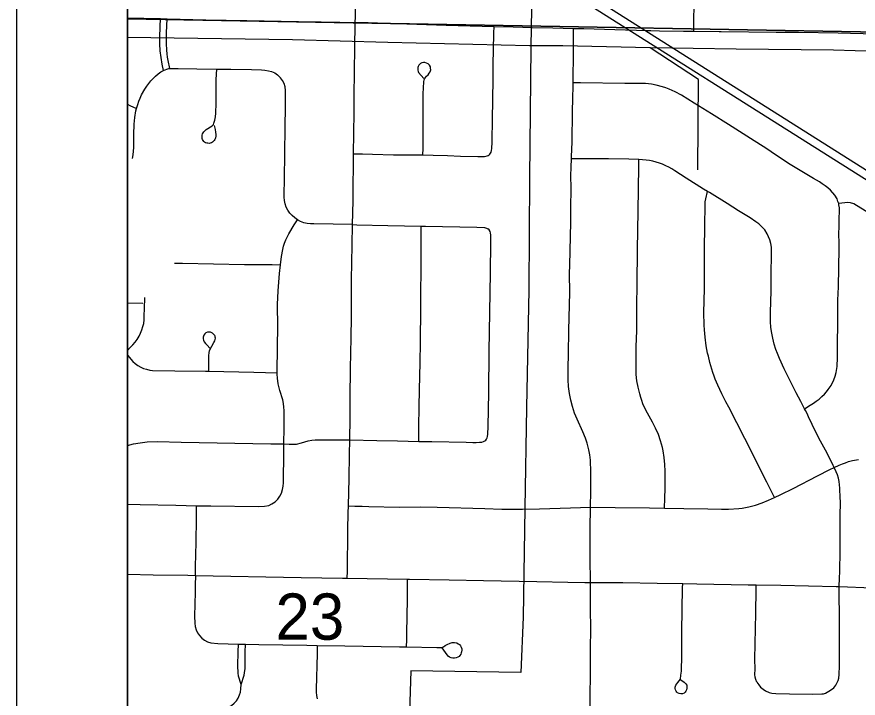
# Model space of a CAD drawing. Extents: x -59 to 43, y 0 to 22.
# Drawn here: x 23.417 to 24.177, y 17.75 to 18.366 of the extents above; entities that cross this region are included whole.
import ezdxf

# ---------------------------------------------------------------- set-up
doc = ezdxf.new("R2010")
doc.units = 0
for name, color, linetype in [('Default', 7, 'Continuous'), ('GM_X_City_Street', 7, 'Continuous'), ('GM_X_County_Road', 7, 'Continuous'), ('GM_X_Interchange_Ramps', 7, 'Continuous'), ('GM_X_Minor_River', 7, 'Continuous'), ('GM_X_Rail_Line', 7, 'Continuous'), ('GM_X_Section_Text', 7, 'Continuous'), ('GM_X_Township_Road', 7, 'Continuous'), ('SH_Data', 7, 'Continuous')]:
    doc.layers.add(name, color=color, linetype=linetype)

msp = doc.modelspace()

# ---------------------------------------------------------------- linework, layer by layer
at = {"layer": 'Default'}
for points in [[(23.51667, 19.36712), (23.51667, 18.36457), (24.19635, 18.35229), (24.21701, 19.34715)], [(23.51667, 18.36457), (23.51667, 17.35203), (23.63449, 17.34676), (24.1786, 17.34343), (24.19635, 18.35229)]]:
    msp.add_lwpolyline(points, close=True, dxfattribs=at)
at = {"layer": 'GM_X_City_Street'}
for points in [[(24.02872, 18.35333), (24.02879, 18.35839), (24.0291, 18.38136), (24.0295, 18.41121), (24.0296, 18.41847)], [(23.71539, 17.85848), (23.71547, 17.86506), (23.7159, 17.9023), (23.71623, 17.91776), (23.71641, 17.92416), (23.71676, 17.93635), (23.71699, 17.94877), (23.71733, 17.9705), (23.71758, 17.98356), (23.71794, 18.00317), (23.71803, 18.02204), (23.71833, 18.0481), (23.7189, 18.07605), (23.71917, 18.09484), (23.71937, 18.12842), (23.71978, 18.15986), (23.72017, 18.17832), (23.72061, 18.19974), (23.72071, 18.21636), (23.72092, 18.22841), (23.72112, 18.24246), (23.72165, 18.2799), (23.72171, 18.29326), (23.72194, 18.31795), (23.72215, 18.33725), (23.72263, 18.36131), (23.72271, 18.36614), (23.72307, 18.3885)], [(23.54923, 18.31778), (23.54819, 18.32346), (23.54708, 18.32952), (23.54627, 18.33563), (23.54583, 18.34177), (23.54582, 18.34793), (23.54625, 18.35716), (23.54661, 18.36474)], [(23.55509, 18.31957), (23.55362, 18.32673), (23.55299, 18.32981), (23.55253, 18.33292), (23.55223, 18.33604), (23.55199, 18.34232), (23.55208, 18.35174), (23.55227, 18.35802), (23.55247, 18.36459)], [(23.84359, 18.24157), (23.84431, 18.24217), (23.84503, 18.24307), (23.84557, 18.24403), (23.84593, 18.24535), (23.84617, 18.24721), (23.84637, 18.25298), (23.84674, 18.27474), (23.84687, 18.29002), (23.84706, 18.29607), (23.84716, 18.30538), (23.84743, 18.32386), (23.8476, 18.33621), (23.84797, 18.35139), (23.84813, 18.35765)], [(23.93517, 17.85479), (23.93488, 17.87685), (23.93491, 17.90321), (23.93525, 17.92269), (23.93563, 17.93734), (23.93573, 17.95442), (23.93526, 17.96531), (23.93474, 17.97002), (23.93387, 17.97465), (23.9323, 17.98073), (23.93084, 17.98521), (23.92844, 17.99099), (23.92327, 18.00227), (23.92093, 18.00795), (23.91899, 18.01375), (23.91747, 18.0197), (23.91629, 18.02574), (23.91549, 18.03184), (23.91503, 18.03794), (23.91524, 18.04878), (23.91538, 18.06117), (23.91548, 18.06889), (23.91566, 18.0751), (23.91572, 18.08287), (23.91656, 18.11698), (23.91646, 18.13408), (23.91654, 18.14181), (23.91743, 18.1806), (23.91741, 18.19301), (23.91768, 18.21162), (23.91762, 18.22249), (23.91781, 18.23022), (23.91812, 18.238), (23.91817, 18.23952), (23.9187, 18.25314), (23.91906, 18.28028), (23.91942, 18.29274), (23.91954, 18.3036), (23.91958, 18.30665), (23.9199, 18.33568), (23.91989, 18.35036), (23.91989, 18.35584)], [(23.78385, 18.24134), (23.78392, 18.2472), (23.7841, 18.2622), (23.784, 18.2716), (23.78398, 18.28416), (23.78416, 18.29661), (23.78448, 18.30754), (23.78489, 18.3093), (23.78538, 18.31054), (23.78608, 18.31148), (23.78716, 18.3127), (23.7885, 18.31395), (23.78953, 18.31535), (23.79031, 18.31666), (23.79064, 18.31744), (23.79084, 18.31843), (23.7908, 18.31987), (23.79051, 18.32118), (23.78965, 18.32262), (23.7885, 18.32373), (23.78718, 18.32451), (23.78554, 18.32496), (23.78435, 18.32496), (23.78296, 18.32473), (23.78159, 18.32405), (23.78065, 18.32327), (23.78004, 18.32245), (23.77946, 18.32151), (23.77922, 18.32056), (23.77909, 18.31941), (23.77917, 18.31818), (23.77942, 18.31695), (23.77987, 18.31588), (23.7846, 18.31042)], [(23.5211, 18.23809), (23.52173, 18.2416), (23.52236, 18.24805), (23.52231, 18.25378), (23.5223, 18.2599), (23.52264, 18.26908), (23.52327, 18.27517), (23.52438, 18.28119), (23.52498, 18.2835), (23.52593, 18.28711), (23.52691, 18.29001), (23.52808, 18.29284), (23.52941, 18.2956), (23.53241, 18.30094), (23.53406, 18.30352), (23.53586, 18.30599), (23.5378, 18.30835), (23.53988, 18.3106), (23.54206, 18.31276), (23.54436, 18.31476), (23.54687, 18.31652), (23.54923, 18.31778), (23.55224, 18.31896)], [(23.55224, 18.31896), (23.55407, 18.31941), (23.55509, 18.31957), (23.56243, 18.3197), (23.57941, 18.31924), (23.59738, 18.31902), (23.61021, 18.31885), (23.62872, 18.3186), (23.63797, 18.31829), (23.64103, 18.31802), (23.64405, 18.31756), (23.647, 18.3168), (23.6498, 18.31557), (23.65232, 18.3138), (23.65497, 18.31109)], [(23.59503, 18.26814), (23.59583, 18.26433), (23.59631, 18.26205), (23.59648, 18.25992), (23.59648, 18.25821), (23.59627, 18.25697), (23.59593, 18.25605), (23.59563, 18.25531), (23.59507, 18.2545), (23.59415, 18.25359), (23.59346, 18.25305), (23.59261, 18.25245), (23.59158, 18.25207), (23.59043, 18.25185), (23.58927, 18.25189), (23.5883, 18.25207), (23.58727, 18.2524), (23.58642, 18.25296), (23.5857, 18.25364), (23.58501, 18.25441), (23.58455, 18.25539), (23.58435, 18.25632), (23.58412, 18.25744), (23.58416, 18.25846), (23.58429, 18.25936), (23.58463, 18.26038), (23.58514, 18.26145), (23.58569, 18.2623), (23.58624, 18.26294), (23.58684, 18.26362), (23.58777, 18.26435), (23.59323, 18.2678), (23.59439, 18.26895), (23.59489, 18.27005), (23.59581, 18.27296), (23.59631, 18.27598), (23.59653, 18.27902), (23.59679, 18.28821), (23.59701, 18.30962), (23.59738, 18.31902)], [(23.72017, 18.17832), (23.68533, 18.17906), (23.68221, 18.17918), (23.67911, 18.17947), (23.67607, 18.18011), (23.67317, 18.18121), (23.67028, 18.18281), (23.66787, 18.18447), (23.66549, 18.18649), (23.66339, 18.18878), (23.66161, 18.19133), (23.66023, 18.19412), (23.65928, 18.19708), (23.65871, 18.20013), (23.65844, 18.20324), (23.6584, 18.20635), (23.65872, 18.21881), (23.659, 18.24373), (23.65927, 18.26529), (23.65936, 18.27182), (23.65945, 18.27938), (23.65955, 18.28732), (23.65965, 18.29668), (23.65954, 18.29981), (23.65915, 18.3029), (23.65831, 18.30587), (23.65685, 18.3086), (23.65497, 18.31109)], [(24.12881, 18.01185), (24.13397, 18.01517), (24.13676, 18.01695), (24.13947, 18.01861), (24.14191, 18.02048), (24.14452, 18.02294), (24.14697, 18.02508), (24.14871, 18.02708), (24.15019, 18.02928), (24.15282, 18.033), (24.15518, 18.03785), (24.1564, 18.04119), (24.15728, 18.0447), (24.15822, 18.04989), (24.15851, 18.05815), (24.15872, 18.06648), (24.15893, 18.09271), (24.15902, 18.11005), (24.15937, 18.1221), (24.16007, 18.15676), (24.16003, 18.16289), (24.15995, 18.16876), (24.16011, 18.178), (24.1602, 18.1842), (24.16041, 18.19036), (24.16031, 18.19339), (24.1599, 18.19636), (24.1597, 18.19752), (24.15905, 18.1994), (24.15826, 18.20158), (24.15629, 18.20489), (24.1523, 18.20954), (24.14998, 18.21157), (24.14749, 18.21344), (24.14488, 18.2152), (24.14223, 18.21692), (24.13681, 18.22009), (24.12624, 18.22638), (24.11574, 18.23284), (24.10246, 18.24136), (24.09457, 18.24677), (24.08004, 18.25621), (24.06016, 18.26884), (24.04465, 18.27863), (24.02914, 18.28823), (24.01761, 18.29529), (24.01197, 18.29835), (24.00638, 18.30095), (24.00349, 18.30208), (24.00047, 18.3031), (23.99477, 18.3046), (23.99046, 18.30541), (23.98488, 18.30597), (23.97258, 18.30593), (23.96645, 18.30587), (23.92612, 18.30654), (23.91958, 18.30665)], [(23.51667, 18.28727), (23.51894, 18.28624), (23.52498, 18.2835)], [(23.72112, 18.24246), (23.7291, 18.24227), (23.73827, 18.24204), (23.75722, 18.24159), (23.77556, 18.24159), (23.78385, 18.24134), (23.79315, 18.24107), (23.80594, 18.24075), (23.81788, 18.24037), (23.83343, 18.24011), (23.83745, 18.23994), (23.83961, 18.24006), (23.8408, 18.24029), (23.84189, 18.2406), (23.84269, 18.24097), (23.84359, 18.24157)], [(24.16021, 17.85099), (24.16044, 17.85853), (24.16062, 17.86473), (24.16077, 17.87093), (24.16087, 17.8771), (24.16095, 17.88323), (24.16094, 17.88934), (24.16102, 17.91014), (24.16112, 17.91696), (24.16121, 17.92518), (24.16094, 17.93382), (24.16086, 17.93689), (24.16066, 17.93996), (24.16034, 17.94303), (24.15997, 17.94608), (24.15941, 17.94909), (24.15857, 17.95203), (24.15746, 17.9549), (24.15573, 17.95861), (24.15483, 17.96052), (24.14915, 17.97156), (24.14318, 17.98241), (24.13897, 17.99071), (24.13235, 18.00465), (24.13108, 18.00747), (24.12967, 18.01013), (24.12881, 18.01185), (24.12558, 18.01827), (24.12127, 18.02612), (24.11041, 18.04792), (24.10619, 18.05724), (24.10438, 18.06176), (24.10288, 18.06537), (24.10137, 18.07018), (24.10007, 18.07569), (24.09926, 18.0801), (24.09846, 18.08532), (24.09815, 18.09074), (24.09815, 18.09926), (24.09852, 18.11814), (24.09872, 18.13348), (24.09873, 18.13961), (24.09893, 18.14556), (24.09905, 18.1517), (24.099, 18.15477), (24.09882, 18.15793), (24.09843, 18.16124), (24.09742, 18.16445), (24.09631, 18.16716), (24.09511, 18.17007), (24.0929, 18.17368), (24.08966, 18.177), (24.08739, 18.1791), (24.08491, 18.18097), (24.07971, 18.18436), (24.06919, 18.19094), (24.05874, 18.19757), (24.04287, 18.20729), (24.04101, 18.20836), (24.03752, 18.21042), (24.02183, 18.2204), (24.01143, 18.22715), (24.00879, 18.22877), (24.00608, 18.23028), (24.0033, 18.23167), (24.00046, 18.23291), (23.99755, 18.23399), (23.99461, 18.23493), (23.99165, 18.2357), (23.98864, 18.23629), (23.98558, 18.23671), (23.97914, 18.23726), (23.9701, 18.23766), (23.9515, 18.23793), (23.92449, 18.23798), (23.91812, 18.238)], [(24.00226, 17.92202), (24.00256, 17.93086), (24.00263, 17.93392), (24.00274, 17.93661), (24.00276, 17.93966), (24.00275, 17.949), (24.0027, 17.95532), (24.00244, 17.96153), (24.00196, 17.96772), (24.00104, 17.97385), (24.00037, 17.97688), (23.99868, 17.98278), (23.99667, 17.98854), (23.99417, 17.99419), (23.99129, 17.99969), (23.98675, 18.00786), (23.98397, 18.01341), (23.98274, 18.01625), (23.98165, 18.01915), (23.98066, 18.02212), (23.97976, 18.02532), (23.97831, 18.03141), (23.97716, 18.03698), (23.97687, 18.03971), (23.97664, 18.04316), (23.97648, 18.04633), (23.97648, 18.05081), (23.97647, 18.05345), (23.97662, 18.0591), (23.9766, 18.06776), (23.97717, 18.08265), (23.97714, 18.08538), (23.97734, 18.1002), (23.97739, 18.12901), (23.97784, 18.15117), (23.97769, 18.156), (23.97826, 18.19063), (23.97902, 18.23097), (23.97914, 18.23726)], [(24.10179, 17.93162), (24.09964, 17.93584), (24.09473, 17.94545), (24.0882, 17.95848), (24.08405, 17.96665), (24.07484, 17.98485), (24.0603, 18.01311), (24.0577, 18.01801), (24.05645, 18.02044), (24.05402, 18.02529), (24.05034, 18.03323), (24.04801, 18.03854), (24.04696, 18.04137), (24.04601, 18.04453), (24.04325, 18.05365), (24.04184, 18.05931), (24.04122, 18.06221), (24.03989, 18.06858), (24.03893, 18.07653), (24.03863, 18.07974), (24.03824, 18.08305), (24.03805, 18.08734), (24.03783, 18.09878), (24.03823, 18.12041), (24.03836, 18.12528), (24.03839, 18.13361), (24.03834, 18.13887), (24.03833, 18.14746), (24.03831, 18.15596), (24.03859, 18.1773), (24.03884, 18.1959), (24.03909, 18.19892), (24.03951, 18.20168), (24.04101, 18.20836)], [(24.1945, 18.18423), (24.17593, 18.19577), (24.17334, 18.1971), (24.17037, 18.19799), (24.16781, 18.19825), (24.16533, 18.19818), (24.1597, 18.19752)], [(23.51667, 17.92562), (23.52808, 17.9252), (23.56037, 17.92469), (23.57907, 17.9241), (23.59194, 17.9239), (23.63516, 17.9233), (23.64058, 17.92361), (23.64456, 17.92443), (23.64732, 17.92576), (23.65008, 17.9276), (23.65263, 17.93016), (23.65436, 17.93272), (23.6559, 17.93557), (23.65684, 17.93871), (23.65751, 17.94173), (23.65778, 17.94484), (23.658, 17.97283), (23.65811, 17.97997), (23.65833, 17.99464), (23.65827, 18.01017), (23.65805, 18.01333), (23.65765, 18.01648), (23.65702, 18.01976), (23.65456, 18.02828), (23.65343, 18.03183), (23.65293, 18.03424), (23.65226, 18.03947), (23.65191, 18.0431), (23.65192, 18.04441), (23.6522, 18.06805), (23.65259, 18.08596), (23.65229, 18.1062), (23.65282, 18.11855), (23.6541, 18.13413), (23.65507, 18.14207), (23.65599, 18.14959), (23.65704, 18.15573), (23.65774, 18.15876), (23.65863, 18.16173), (23.65976, 18.16462), (23.66271, 18.17012), (23.6675, 18.17816), (23.67028, 18.18281)], [(23.72017, 18.17832), (23.72406, 18.17824), (23.7522, 18.17765), (23.78222, 18.17703), (23.78611, 18.17695), (23.83267, 18.17614), (23.83941, 18.17583), (23.84121, 18.17529), (23.84246, 18.17466)], [(23.78006, 17.98235), (23.78001, 17.98779), (23.77996, 17.99401), (23.78027, 18.01507), (23.78064, 18.02751), (23.78099, 18.04279), (23.78117, 18.05209), (23.78163, 18.07326), (23.78201, 18.10118), (23.78204, 18.10429), (23.78219, 18.14959), (23.78222, 18.15257), (23.78227, 18.15561), (23.78231, 18.16181), (23.78235, 18.16785), (23.78231, 18.17048), (23.78222, 18.17703)], [(23.84076, 17.98346), (23.84141, 17.98446), (23.84186, 17.98545), (23.8421, 17.98668), (23.84237, 17.98874), (23.8427, 17.99574), (23.84331, 18.02657), (23.84368, 18.06359), (23.84499, 18.13472), (23.84519, 18.16229), (23.84515, 18.16893), (23.84488, 18.17099), (23.84452, 18.17224), (23.84371, 18.1735), (23.84246, 18.17466)], [(23.55919, 18.14346), (23.56636, 18.1434), (23.62247, 18.14236), (23.64741, 18.14214), (23.65507, 18.14207)], [(23.51667, 18.06456), (23.51927, 18.06727), (23.5215, 18.06956), (23.52358, 18.07199), (23.52546, 18.07459), (23.52714, 18.07732), (23.52857, 18.08019), (23.52974, 18.08316), (23.53057, 18.08624), (23.53136, 18.08892), (23.53179, 18.09212), (23.5319, 18.09597), (23.532, 18.10237), (23.53231, 18.11253)], [(23.5904, 18.04584), (23.5903, 18.05381), (23.59023, 18.0598), (23.59049, 18.06281), (23.59078, 18.0642), (23.59139, 18.06573), (23.59283, 18.06835), (23.59482, 18.07167), (23.59571, 18.07338), (23.59605, 18.0746), (23.59615, 18.07577), (23.5961, 18.07663), (23.59594, 18.07741), (23.59562, 18.07811), (23.5949, 18.07907), (23.59428, 18.07967), (23.59364, 18.08014), (23.5929, 18.08061), (23.59187, 18.08096), (23.59068, 18.08114), (23.58904, 18.08097), (23.58766, 18.08037), (23.58663, 18.07953), (23.58582, 18.07846), (23.58542, 18.07756), (23.58514, 18.07651), (23.58511, 18.07511), (23.58544, 18.07385), (23.58607, 18.07242), (23.58709, 18.07091), (23.58836, 18.06957), (23.59136, 18.0663)], [(23.51667, 18.06028), (23.52158, 18.05467), (23.52379, 18.05268), (23.52607, 18.05089), (23.52887, 18.04945), (23.53132, 18.04834), (23.53392, 18.04748), (23.53693, 18.04679), (23.53926, 18.04652), (23.55949, 18.04607), (23.58736, 18.0459), (23.5904, 18.04584), (23.63107, 18.04482), (23.65192, 18.04441)], [(23.51667, 17.97844), (23.52218, 17.97996), (23.52827, 17.98113), (23.53444, 17.98178), (23.54375, 17.9821), (23.56538, 17.98147), (23.64624, 17.97995), (23.65811, 17.97997), (23.66298, 17.97965), (23.66962, 17.97992), (23.67388, 17.98085), (23.68009, 17.98275), (23.68345, 17.98338), (23.68624, 17.98365), (23.68934, 17.98361), (23.71418, 17.98361), (23.71758, 17.98356), (23.7421, 17.98321), (23.76069, 17.98274), (23.78006, 17.98235), (23.79173, 17.98212), (23.82275, 17.9815), (23.82889, 17.98136), (23.83195, 17.98136), (23.835, 17.98149), (23.83718, 17.98167), (23.83866, 17.98211), (23.83981, 17.98281), (23.84076, 17.98346)], [(23.71641, 17.92416), (23.72232, 17.92386), (23.7289, 17.9237), (23.73505, 17.92354), (23.76234, 17.92288), (23.78138, 17.92303), (23.79676, 17.92278), (23.83971, 17.9216), (23.8552, 17.92112), (23.87382, 17.92115), (23.88934, 17.9214), (23.91725, 17.9223), (23.93525, 17.92269), (23.9576, 17.92262), (23.98865, 17.92221), (24.00226, 17.92202), (24.01969, 17.92158), (24.04141, 17.92127), (24.05382, 17.9209), (24.06002, 17.92101), (24.06931, 17.92167), (24.0724, 17.92205), (24.0785, 17.92321), (24.08453, 17.92473), (24.09041, 17.92671), (24.09617, 17.92902), (24.10179, 17.93162), (24.10744, 17.93423), (24.11854, 17.9398), (24.14057, 17.95128), (24.15171, 17.95675), (24.15573, 17.95861), (24.16017, 17.96066), (24.16302, 17.96188), (24.16593, 17.96294), (24.1686, 17.96398), (24.17221, 17.96499), (24.17763, 17.9659)], [(23.57818, 17.86105), (23.57832, 17.86905), (23.57871, 17.89083), (23.5791, 17.91254), (23.57907, 17.91876), (23.57907, 17.9241)], [(23.57818, 17.86105), (23.57803, 17.85216), (23.57794, 17.84595), (23.57734, 17.82422), (23.57746, 17.81801), (23.57786, 17.81493), (23.57868, 17.81194), (23.58001, 17.80914), (23.58181, 17.80661), (23.58394, 17.80435), (23.5864, 17.80248), (23.58918, 17.8011), (23.59215, 17.8002), (23.5983, 17.79936), (23.60761, 17.79908), (23.61712, 17.7989), (23.62339, 17.79878), (23.63553, 17.79855), (23.67893, 17.79798), (23.68825, 17.79779), (23.71308, 17.79728), (23.76274, 17.79654), (23.76893, 17.79651), (23.79635, 17.79576), (23.80043, 17.79596), (23.80142, 17.79618), (23.80227, 17.7966), (23.80393, 17.79756), (23.80572, 17.79855), (23.80834, 17.79974), (23.81029, 17.80034), (23.81248, 17.80042), (23.81438, 17.80002), (23.8157, 17.79931), (23.81689, 17.79847), (23.81776, 17.7974), (23.81844, 17.79617), (23.81891, 17.79474), (23.81903, 17.79347), (23.8188, 17.792), (23.81852, 17.79093), (23.81796, 17.78981), (23.81725, 17.78866), (23.81642, 17.78782), (23.8153, 17.78703), (23.81375, 17.7864), (23.81228, 17.78615), (23.81077, 17.78619), (23.80942, 17.78655), (23.80795, 17.78722), (23.80676, 17.7881), (23.80577, 17.78925), (23.80117, 17.79573)], [(23.76893, 17.79651), (23.76912, 17.80271), (23.76932, 17.80883), (23.76968, 17.82431), (23.76988, 17.83969), (23.76994, 17.85124), (23.76997, 17.85767)], [(24.01708, 17.76664), (24.02011, 17.76455), (24.02159, 17.7629), (24.02233, 17.7617), (24.02251, 17.76035), (24.02251, 17.75899), (24.02211, 17.75758), (24.02156, 17.75641), (24.02088, 17.75541), (24.01985, 17.75459), (24.01853, 17.7541), (24.0169, 17.754), (24.01559, 17.75423), (24.01409, 17.75482), (24.0135, 17.7554), (24.01274, 17.75636), (24.01228, 17.75749), (24.01192, 17.75885), (24.01196, 17.76007), (24.0126, 17.76188), (24.01327, 17.76301), (24.01436, 17.76437), (24.01558, 17.76573), (24.01653, 17.76713), (24.01708, 17.77072), (24.01756, 17.77434), (24.01772, 17.7778), (24.01788, 17.78529), (24.01795, 17.81032), (24.01857, 17.84984), (24.01864, 17.85376)], [(24.08582, 17.76465), (24.08476, 17.76685), (24.08412, 17.76897), (24.08391, 17.77151), (24.08405, 17.77619), (24.0839, 17.78545), (24.08478, 17.82688), (24.08505, 17.84848), (24.0851, 17.85255)], [(24.15703, 17.76187), (24.15829, 17.76421), (24.15906, 17.76598), (24.15977, 17.76824), (24.1602, 17.77135), (24.16034, 17.77927), (24.16046, 17.78554), (24.16033, 17.79527), (24.16042, 17.80456), (24.16044, 17.81712), (24.16021, 17.85099)], [(23.61936, 17.76247), (23.61719, 17.7701), (23.61668, 17.773), (23.61648, 17.77936), (23.6169, 17.79205), (23.61712, 17.7989)], [(23.61936, 17.76247), (23.62229, 17.77091), (23.62261, 17.77287), (23.62295, 17.7768), (23.62321, 17.7918), (23.62339, 17.79878)], [(23.68825, 17.79779), (23.68805, 17.79012), (23.68721, 17.75826), (23.68722, 17.75546), (23.68757, 17.75247), (23.68821, 17.74955)], [(23.51667, 17.74135), (23.55837, 17.74057), (23.56836, 17.74038), (23.58069, 17.74018), (23.59923, 17.73968), (23.6023, 17.73993), (23.6053, 17.74066), (23.60813, 17.74189), (23.61081, 17.74345), (23.6132, 17.7454), (23.61519, 17.74775), (23.6168, 17.75015), (23.61803, 17.753), (23.61883, 17.7556), (23.61921, 17.75858), (23.61936, 17.76247)], [(24.08582, 17.76465), (24.08741, 17.76205), (24.08912, 17.76014), (24.09145, 17.75817), (24.0935, 17.75675), (24.0969, 17.7552), (24.09909, 17.75463), (24.10291, 17.75428), (24.11522, 17.754), (24.13574, 17.75366), (24.14437, 17.75387), (24.146, 17.75408), (24.14769, 17.75465), (24.15075, 17.7563), (24.15308, 17.75776), (24.15519, 17.75947), (24.15703, 17.76187)]]:
    msp.add_lwpolyline(points, dxfattribs=at)
at = {"layer": 'GM_X_County_Road'}
for p, q in [((23.51667, 18.36535), (23.54661, 18.36474)), ((24.02872, 18.35333), (24.05155, 18.35317))]:
    msp.add_line(p, q, dxfattribs=at)
for points in [[(23.54661, 18.36474), (23.55247, 18.36459), (23.58745, 18.36367), (23.62475, 18.36305), (23.67136, 18.36215), (23.69183, 18.36185), (23.70866, 18.3616), (23.72263, 18.36131)], [(23.72263, 18.36131), (23.73443, 18.36105), (23.74283, 18.36087), (23.80495, 18.35883), (23.84813, 18.35765)], [(23.84813, 18.35765), (23.86537, 18.35717), (23.88251, 18.35671), (23.90126, 18.35627), (23.91989, 18.35584)], [(23.91989, 18.35584), (23.92924, 18.35563), (23.95719, 18.35487), (23.98642, 18.35403), (23.9897, 18.35394), (23.99759, 18.35371), (24.01935, 18.3534), (24.02872, 18.35333)], [(24.05155, 18.35317), (24.05354, 18.35315), (24.10325, 18.35249), (24.12329, 18.35228), (24.15918, 18.3519), (24.19308, 18.35084), (24.20267, 18.35054), (24.22887, 18.34957), (24.26357, 18.34829)]]:
    msp.add_lwpolyline(points, dxfattribs=at)
at = {"layer": 'GM_X_Interchange_Ramps'}
msp.add_lwpolyline([(23.51667, 20.9), (23.51667, 15.35309)], dxfattribs=at)
at = {"layer": 'GM_X_Minor_River'}
msp.add_line((23.53073, 18.10693), (23.51667, 18.10736), dxfattribs=at)
for points in [[(23.72431, 18.99082), (23.72802, 18.98656), (23.73721, 18.97081), (23.73786, 18.96547), (23.73947, 18.95024), (23.73906, 18.92858), (23.73879, 18.91414), (23.73965, 18.89968), (23.74168, 18.88672), (23.75276, 18.87092), (23.7661, 18.85433), (23.78065, 18.84151), (23.80083, 18.82516), (23.82139, 18.80919), (23.81905, 18.72599), (23.81499, 18.57213), (23.81158, 18.4726), (23.81717, 18.46756), (23.82762, 18.45824), (23.88276, 18.42527), (23.8815, 18.33901), (23.88001, 18.22082), (23.8796, 18.11934)], [(24.28106, 18.2836), (24.2528, 18.33316), (24.15497, 18.33614), (24.06698, 18.33704), (23.98922, 18.33812), (23.91035, 18.33998), (23.88019, 18.34013), (23.75221, 18.34297), (23.66576, 18.34536), (23.55881, 18.34701), (23.51667, 18.34767)], [(24.03227, 18.22784), (24.03307, 18.30955), (23.98922, 18.33812)], [(23.8796, 18.11934), (23.87758, 18.01295), (23.87585, 17.92176), (23.87436, 17.82334), (23.87226, 17.77321), (23.7729, 17.7747), (23.77017, 17.69075), (23.77063, 17.63525)]]:
    msp.add_lwpolyline(points, dxfattribs=at)
at = {"layer": 'GM_X_Rail_Line'}
for points in [[(24.85953, 17.57035), (24.84019, 17.76617), (24.82935, 17.81016), (24.79303, 17.84892), (24.19874, 18.21842), (23.51667, 18.64966)], [(23.51667, 18.64098), (24.21418, 18.20034), (24.75495, 17.86208), (24.75829, 17.57829), (24.85953, 17.57035)]]:
    msp.add_lwpolyline(points, dxfattribs=at)
at = {"layer": 'GM_X_Township_Road'}
msp.add_line((23.71539, 17.85848), (23.76997, 17.85767), dxfattribs=at)
for points in [[(23.51667, 17.86207), (23.54007, 17.86167), (23.57118, 17.86118), (23.57818, 17.86105)], [(23.57818, 17.86105), (23.67375, 17.85926), (23.71106, 17.85854), (23.71539, 17.85848)], [(23.76997, 17.85767), (23.77168, 17.85764), (23.80744, 17.85696), (23.83854, 17.85645), (23.88673, 17.85556), (23.91472, 17.85506), (23.93025, 17.85478), (23.93517, 17.85479)], [(23.93507, 17.73872), (23.9351, 17.74532), (23.93521, 17.77838), (23.93542, 17.79526), (23.93557, 17.81221), (23.9354, 17.83145), (23.93522, 17.84938), (23.93517, 17.85479)], [(23.93517, 17.85479), (23.96446, 17.8548), (23.99556, 17.85421), (24.01864, 17.85376)], [(24.01864, 17.85376), (24.03131, 17.85352), (24.07796, 17.85267), (24.0851, 17.85255)], [(24.0851, 17.85255), (24.1075, 17.85215), (24.15726, 17.85109), (24.16021, 17.85099)], [(24.16021, 17.85099), (24.18989, 17.84998), (24.21681, 17.84902)]]:
    msp.add_lwpolyline(points, dxfattribs=at)
at = {"layer": 'SH_Data'}
for points in [[(23.41667, 21), (30.41667, 21), (30.41667, 14), (23.41667, 14)], [(23.51667, 20.9), (30.31667, 20.9), (30.31667, 14.1), (23.51667, 14.1)]]:
    msp.add_lwpolyline(points, close=True, dxfattribs=at)

# ---------------------------------------------------------------- texts
at = {"layer": 'GM_X_Section_Text'}
msp.add_text('23', height=0.041856, rotation=0.00001, dxfattribs=at).set_placement((23.65047, 17.80291))

doc.saveas('drawing.dxf')
